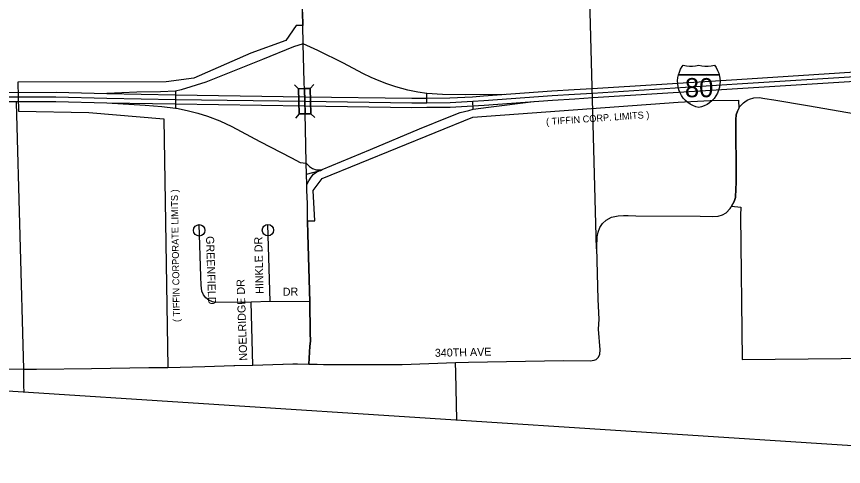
# Model space of a CAD drawing. Extents: x 281.94 to 289.14, y 116.09 to 120.89.
# Drawn here: x 283.686 to 285.132, y 117.245 to 118.031 of the extents above; entities that cross this region are included whole.
import ezdxf

# ---------------------------------------------------------------- set-up
doc = ezdxf.new("R2010")
doc.units = 0
for name, color, linetype in [('tdCiCityCuldesac', 7, 'Continuous'), ('tdCiCityStreetCL', 7, 'Continuous'), ('tdCiCityStreetTxt', 7, 'Continuous'), ('tdCiCorpBndry', 7, 'Continuous'), ('tdCiCorpBndryPart', 7, 'Continuous'), ('tdCiCorpBndryTxt', 7, 'Continuous'), ('tdCiInt', 7, 'Continuous'), ('tdCiIntCL', 7, 'Continuous'), ('tdCiIntRamp', 7, 'Continuous'), ('tdCiIntRampCL', 7, 'Continuous'), ('tdCiMapPltShpe', 7, 'Continuous'), ('tdCiSecCL', 7, 'Continuous'), ('tdCiSecText', 7, 'Continuous'), ('tdCiSectLine', 7, 'Continuous'), ('tdCiShieldInt', 7, 'Continuous'), ('tdCiStrucDataMuni', 7, 'Continuous')]:
    doc.layers.add(name, color=color, linetype=linetype)

msp = doc.modelspace()

# ---------------------------------------------------------------- linework, layer by layer
at = {"layer": 'tdCiCityCuldesac'}
for centre in [(284.0058, 117.6572), (284.1259, 117.6576)]:
    msp.add_circle(centre, 0.01, dxfattribs=at)
at = {"layer": 'tdCiCityStreetCL'}
for points in [[(284.1952, 117.674), (284.1948, 117.7038), (284.1941, 117.7277), (284.1938, 117.7376), (284.1934, 117.7552), (284.1929, 117.7749), (284.1922, 117.8054), (284.1907, 117.8622), (284.1901, 117.8828), (284.1896, 117.9034), (284.1892, 117.9164), (284.1875, 117.9834), (284.1867, 118.0153)], [(284.9488, 117.8699), (284.951, 117.8738), (284.9569, 117.8798), (284.9621, 117.8834), (284.9645, 117.8852), (284.9678, 117.8864), (284.9754, 117.8886), (284.9843, 117.8894), (284.9946, 117.8878), (285.0104, 117.8854), (285.0689, 117.8753), (285.1527, 117.8608), (285.2097, 117.8533), (285.2193, 117.8523)], [(284.0965, 117.5318), (284.0351, 117.5312), (284.029, 117.5322), (284.0223, 117.5352), (284.0171, 117.5396), (284.0131, 117.5445), (284.0102, 117.5509), (284.009, 117.5616), (284.0087, 117.5768), (284.0055, 117.6672)], [(284.1296, 117.5327), (284.1256, 117.6676)], [(284.1296, 117.5327), (284.0965, 117.5318)], [(284.0997, 117.4217), (284.0965, 117.5318)], [(284.1991, 117.5324), (284.1296, 117.5327)]]:
    msp.add_lwpolyline(points, dxfattribs=at)
at = {"layer": 'tdCiCorpBndry'}
msp.add_lwpolyline([(284.1861, 118.0386), (284.1867, 118.0153), (284.1753, 118.0153), (284.1569, 117.9891), (284.0959, 117.9671), (283.9964, 117.9231), (283.9481, 117.9168), (283.6885, 117.916), (283.6891, 117.8903), (283.6897, 117.8655), (283.8128, 117.863), (283.9437, 117.852), (283.951, 117.4177), (284.0158, 117.4194), (284.0661, 117.421), (284.0682, 117.421), (284.0997, 117.4217), (284.1697, 117.4238), (284.1776, 117.424), (284.1976, 117.4236), (284.1994, 117.4551), (284.2001, 117.4635), (284.1999, 117.4783), (284.1991, 117.5324), (284.1956, 117.6505), (284.1952, 117.674), (284.2076, 117.6741), (284.2051, 117.727), (284.2208, 117.748), (284.4842, 117.8547), (284.8428, 117.8812), (284.899, 117.8841), (284.9486, 117.8849), (284.9488, 117.8699), (284.9466, 117.8657), (284.9443, 117.8593), (284.9436, 117.8511), (284.9439, 117.8172), (284.9441, 117.7789), (284.9443, 117.7434), (284.9435, 117.7268), (284.9432, 117.7176), (284.9429, 117.7145), (284.9409, 117.7074), (284.9362, 117.6992), (284.9523, 117.6977), (284.9522, 117.6832), (284.955, 117.4315), (285.7041, 117.4389)], dxfattribs=at)
at = {"layer": 'tdCiCorpBndryPart'}
for points in [[(284.1867, 118.0153), (284.1753, 118.0153), (284.1569, 117.9891), (284.0959, 117.9671), (283.9964, 117.9231), (283.9481, 117.9168), (283.6885, 117.916), (283.6891, 117.8903), (283.6897, 117.8655), (283.8128, 117.863), (283.9437, 117.852), (283.951, 117.4177)], [(284.1952, 117.674), (284.2076, 117.6741), (284.2051, 117.727), (284.2208, 117.748), (284.4842, 117.8547), (284.8428, 117.8812), (284.899, 117.8841), (284.9486, 117.8849), (284.9488, 117.8699)], [(284.9362, 117.6992), (284.9362, 117.6992), (284.9523, 117.6977), (284.9522, 117.6832), (284.955, 117.4315), (285.7041, 117.4389)]]:
    msp.add_lwpolyline(points, dxfattribs=at)
at = {"layer": 'tdCiInt'}
for points in [[(283.6583, 117.8986), (283.6891, 117.8983), (283.7555, 117.8986), (283.8444, 117.8962), (283.9644, 117.894), (284.1903, 117.8908), (284.3775, 117.8881), (284.4035, 117.8883), (284.4441, 117.8885), (284.4833, 117.8907), (284.5029, 117.892), (284.6224, 117.9009), (284.6613, 117.9032), (284.6926, 117.9052), (284.9454, 117.921), (285.1697, 117.9351)], [(283.6581, 117.8826), (283.6891, 117.8823), (283.7553, 117.8826), (283.8441, 117.8802), (283.9641, 117.8781), (284.19, 117.8748), (284.3775, 117.8721), (284.4036, 117.8723), (284.4446, 117.8725), (284.4843, 117.8747), (284.504, 117.8761), (284.6235, 117.8849), (284.6622, 117.8873), (284.6936, 117.8892), (284.9464, 117.9051), (285.1707, 117.9191)]]:
    msp.add_lwpolyline(points, dxfattribs=at)
at = {"layer": 'tdCiIntCL'}
msp.add_lwpolyline([(283.6582, 117.8906), (283.6891, 117.8903), (283.7554, 117.8906), (283.8442, 117.8882), (283.9642, 117.886), (284.1901, 117.8828), (284.3775, 117.8801), (284.4035, 117.8803), (284.4444, 117.8805), (284.4838, 117.8827), (284.5035, 117.8841), (284.623, 117.8929), (284.6618, 117.8952), (284.6931, 117.8972), (284.9459, 117.9131), (285.1702, 117.9271)], dxfattribs=at)
at = {"layer": 'tdCiIntRamp'}
for points in [[(284.1875, 117.9834), (284.1708, 117.9776), (284.1163, 117.9559), (284.0176, 117.9159), (283.9745, 117.9028), (283.9642, 117.9007), (283.9381, 117.8994), (283.8967, 117.8985), (283.8443, 117.8962)], [(284.5389, 117.8947), (284.472, 117.8938), (284.4311, 117.8948), (284.4038, 117.8961), (284.388, 117.8986), (284.3705, 117.9023), (284.3495, 117.9078), (284.334, 117.9132), (284.3202, 117.9184), (284.3061, 117.9243), (284.2918, 117.931), (284.2581, 117.9494), (284.2134, 117.9716), (284.1875, 117.9834)], [(283.8441, 117.8802), (283.9113, 117.8762), (283.9406, 117.8739), (283.9645, 117.8707), (283.9658, 117.8705), (283.9848, 117.8668), (284.0036, 117.8622), (284.0201, 117.8567), (284.042, 117.8483), (284.063, 117.8387), (284.1116, 117.8126), (284.1668, 117.7837), (284.1823, 117.7758), (284.1929, 117.7749)], [(284.1938, 117.7376), (284.1976, 117.744), (284.2014, 117.7503), (284.2057, 117.7552), (284.2113, 117.7594), (284.2208, 117.7635), (284.3052, 117.7985), (284.391, 117.8345), (284.4425, 117.8555), (284.4622, 117.8629), (284.4768, 117.8668), (284.4848, 117.8687), (284.5115, 117.8726), (284.5899, 117.8824)], [(284.1929, 117.7749), (284.1985, 117.769), (284.204, 117.7651), (284.2102, 117.7632), (284.2161, 117.763), (284.2208, 117.7635)]]:
    msp.add_lwpolyline(points, dxfattribs=at)
at = {"layer": 'tdCiIntRampCL'}
for points in [[(284.4035, 117.8803), (284.4038, 117.8961), (284.388, 117.8986), (284.3705, 117.9023), (284.3495, 117.9078), (284.334, 117.9132), (284.3202, 117.9184), (284.3061, 117.9243), (284.2918, 117.931), (284.2581, 117.9494), (284.2134, 117.9716), (284.1875, 117.9834), (284.1708, 117.9776), (284.1163, 117.9559), (284.0176, 117.9159), (283.9745, 117.9028), (283.9642, 117.9007), (283.9642, 117.886), (283.9645, 117.8707), (283.9658, 117.8705), (283.9848, 117.8668), (284.0036, 117.8622), (284.0201, 117.8567), (284.042, 117.8483), (284.063, 117.8387), (284.1116, 117.8126), (284.1668, 117.7837), (284.1823, 117.7758), (284.1929, 117.7749)], [(284.1934, 117.7552), (284.2175, 117.7617), (284.2208, 117.7635), (284.3052, 117.7985), (284.391, 117.8345), (284.4425, 117.8555), (284.4622, 117.8629), (284.4768, 117.8668), (284.4848, 117.8687), (284.4838, 117.8827)]]:
    msp.add_lwpolyline(points, dxfattribs=at)
at = {"layer": 'tdCiMapPltShpe'}
msp.add_line((283.629, 117.3793), (285.715, 117.2447), dxfattribs=at)
at = {"layer": 'tdCiSecCL'}
for points in [[(284.1867, 118.0153), (284.1861, 118.0386), (284.1841, 118.1097), (284.1827, 118.1651), (284.1793, 118.2822), (284.1781, 118.3291), (284.1778, 118.3364), (284.1775, 118.3482), (284.1771, 118.3606), (284.1757, 118.4265)], [(284.4538, 117.4262), (284.4763, 117.427), (284.6427, 117.4297), (284.6891, 117.4294), (284.6963, 117.4304), (284.6997, 117.4317), (284.7021, 117.4341), (284.7036, 117.4356), (284.7061, 117.441), (284.7069, 117.4487), (284.7039, 117.4847), (284.7046, 117.5018), (284.7029, 117.5365), (284.7007, 117.627), (284.7014, 117.6457), (284.7029, 117.6541), (284.7061, 117.662), (284.7106, 117.6691), (284.717, 117.6753), (284.7266, 117.6802), (284.7379, 117.6825), (284.7473, 117.6832), (284.7557, 117.6834), (284.7688, 117.6825), (284.8817, 117.682), (284.9032, 117.6817), (284.9128, 117.6822), (284.9207, 117.6842), (284.9271, 117.6881), (284.9337, 117.6955), (284.9351, 117.6973), (284.9362, 117.6992), (284.9409, 117.7074), (284.9429, 117.7145), (284.9432, 117.7176), (284.9435, 117.7268), (284.9443, 117.7434), (284.9441, 117.7789), (284.9439, 117.8172), (284.9436, 117.8511), (284.9443, 117.8593), (284.9466, 117.8657), (284.9488, 117.8699)], [(284.1952, 117.674), (284.1956, 117.6505), (284.1991, 117.5324), (284.1999, 117.4783), (284.2001, 117.4635), (284.1994, 117.4551), (284.1976, 117.4236), (284.2117, 117.4233), (284.2228, 117.423), (284.2898, 117.423), (284.3604, 117.423), (284.4538, 117.4262)], [(283.594, 117.4155), (283.6033, 117.4156), (283.6993, 117.4146)], [(283.6993, 117.4146), (283.7214, 117.4144), (283.8173, 117.4159), (283.9175, 117.4174), (283.9511, 117.4177), (284.0158, 117.4194), (284.0661, 117.421), (284.0682, 117.421), (284.0997, 117.4217), (284.1701, 117.4238), (284.1776, 117.424), (284.1976, 117.4236)], [(283.6996, 117.3748), (283.6993, 117.3858), (283.6993, 117.4146)], [(284.4558, 117.326), (284.4542, 117.408), (284.4538, 117.4262)]]:
    msp.add_lwpolyline(points, dxfattribs=at)
at = {"layer": 'tdCiSectLine'}
msp.add_line((283.6993, 117.4146), (283.6866, 117.8808), dxfattribs=at)
msp.add_lwpolyline([(284.7005, 117.6247), (284.6788, 118.4309), (284.6579, 119.4326), (284.6484, 120.235)], dxfattribs=at)
at = {"layer": 'tdCiShieldInt'}
msp.add_line((284.8434, 117.9287), (284.9148, 117.9287), dxfattribs=at)
for points in [[(284.8654, 117.9441), (284.8681, 117.9441), (284.8735, 117.9447), (284.8791, 117.946), (284.8844, 117.9447), (284.8898, 117.9441), (284.8952, 117.9441), (284.9006, 117.9447), (284.9063, 117.946), (284.9094, 117.9416), (284.9119, 117.9368), (284.9139, 117.9318), (284.9148, 117.9287), (284.9159, 117.9234), (284.9163, 117.918), (284.916, 117.9125), (284.9152, 117.9072), (284.9137, 117.902), (284.9116, 117.8969), (284.909, 117.8922), (284.9058, 117.8878), (284.9021, 117.8838), (284.898, 117.8803), (284.8935, 117.8773), (284.8887, 117.8748), (284.8836, 117.8729), (284.8791, 117.8717), (284.8739, 117.8731), (284.8688, 117.8751), (284.8641, 117.8777), (284.8596, 117.8808), (284.8556, 117.8844), (284.852, 117.8884), (284.8489, 117.8929), (284.8463, 117.8977), (284.8443, 117.9027), (284.8429, 117.908), (284.8421, 117.9133), (284.842, 117.9187), (284.8425, 117.9242), (284.8434, 117.9287), (284.8451, 117.9339), (284.8473, 117.9388), (284.8501, 117.9434), (284.852, 117.946), (284.8573, 117.9447), (284.8626, 117.9441)], [(284.8434, 117.9287), (284.8451, 117.9339), (284.8473, 117.9388), (284.8501, 117.9434), (284.852, 117.946), (284.8573, 117.9447), (284.8626, 117.9441), (284.8681, 117.9441), (284.8735, 117.9447), (284.8791, 117.946), (284.8844, 117.9447), (284.8898, 117.9441), (284.8952, 117.9441), (284.9006, 117.9447), (284.9063, 117.946), (284.9094, 117.9416), (284.9119, 117.9368), (284.9139, 117.9318), (284.9148, 117.9287)], [(284.8791, 117.8717), (284.8739, 117.8731), (284.8688, 117.8751), (284.8641, 117.8777), (284.8596, 117.8808), (284.8556, 117.8844), (284.852, 117.8884), (284.8489, 117.8929), (284.8463, 117.8977), (284.8443, 117.9027), (284.8429, 117.908), (284.8421, 117.9133), (284.842, 117.9187), (284.8425, 117.9242), (284.8434, 117.9287), (284.9148, 117.9287), (284.9159, 117.9234), (284.9163, 117.918), (284.916, 117.9125), (284.9152, 117.9072), (284.9137, 117.902), (284.9116, 117.8969), (284.909, 117.8922), (284.9058, 117.8878), (284.9021, 117.8838), (284.898, 117.8803), (284.8935, 117.8773), (284.8887, 117.8748), (284.8836, 117.8729)]]:
    msp.add_lwpolyline(points, close=True, dxfattribs=at)
at = {"layer": 'tdCiStrucDataMuni'}
for points in [[(284.1996, 117.9051), (284.1896, 117.9048), (284.1796, 117.9046), (284.1723, 117.9114)], [(284.2007, 117.8611), (284.1996, 117.9051), (284.2064, 117.9123)], [(284.1796, 117.9046), (284.1807, 117.8606), (284.1739, 117.8533)], [(284.1896, 117.9048), (284.1901, 117.8828), (284.1907, 117.8608)], [(284.1807, 117.8606), (284.1907, 117.8608), (284.2007, 117.8611), (284.208, 117.8542)]]:
    msp.add_lwpolyline(points, dxfattribs=at)
msp.add_lwpolyline([(284.1996, 117.9051), (284.2007, 117.8611), (284.1807, 117.8606), (284.1796, 117.9046)], close=True, dxfattribs=at)

# ---------------------------------------------------------------- texts
at = {"layer": 'tdCiCityStreetTxt'}
for s, rotation, p in [('GREENFIELD', 271.8685, (284.0176, 117.6469)), ('HINKLE DR', 91.4841, (284.1184, 117.5464)), ('NOELRIDGE DR', 92.0715, (284.0899, 117.4298)), ('DR', 0.7773, (284.1519, 117.5429))]:
    msp.add_text(s, height=0.014, rotation=rotation, dxfattribs=at).set_placement(p)
at = {"layer": 'tdCiCorpBndryTxt'}
for s, rotation, p in [('( TIFFIN CORP. LIMITS )', 3.9843, (284.6124, 117.841)), ('( TIFFIN CORPORATE LIMITS )', 90.9776, (283.9722, 117.4972))]:
    msp.add_text(s, height=0.012, rotation=rotation, dxfattribs=at).set_placement(p)
at = {"layer": 'tdCiSecText'}
msp.add_text('340TH AVE', height=0.014, rotation=1.251, dxfattribs=at).set_placement((284.4178, 117.4362))
at = {"layer": 'tdCiShieldInt'}
msp.add_text('80', height=0.03348, dxfattribs=at).set_placement((284.8547, 117.8898))

doc.saveas('drawing.dxf')
